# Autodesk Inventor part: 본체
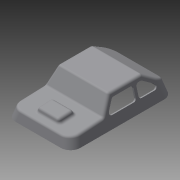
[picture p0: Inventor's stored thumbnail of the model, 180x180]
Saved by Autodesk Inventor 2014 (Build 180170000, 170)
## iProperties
Created: 2015-05
Part Number: 본체
Material: 일반
Document SubType Name: Modeling
Designer: net
Density: 1 g/cm^3
Appearance: 기본값
Author: net
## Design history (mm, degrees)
sketch "스케치1"
  geometry: L1 (0, 0)-(-76, 0); L2 (-76, 0)-(-67.694, 31); L3 (-67.694, 31)-(-8.306, 31); L4 (-8.306, 31)-(0, 0)
  constraints: 8 end point, 1 horizontal, 1 parallel
  dimensions: "d0" = 76 distance of L1.start L1.end; "d1" = 105 deg angle of L1 L2; "d2" = 105 deg angle of L1 L4; "d3" = 31 distance between parallel lines of L1 L3
extrude "돌출1" new body sketch "스케치1" distance "d4" = 122; taper "d5" = 0 deg
node "작업 평면1"
sketch "스케치2"
  geometry: L1 (0, 31)-(0, 0) reference; L2 (0, 31)-(122, 31) reference; L3 (122, 0)-(122, 31) reference; L4 (0, 0)-(122, 0) reference; L5 (0, 0)-(2.978, 11.113); L6 (2.978, 11.113)-(42, 13.158); L7 (42, 13.158)-(53.149, 31); L8 (92, 31)-(118.412, 13.392); L9 (118.412, 13.392)-(122, 0); 1 further point
  constraints: 10 end point, 2 point on line
  dimensions: "d7" = 105 deg angle of L4 L5; "d8" = 3 deg angle of L4 L6; "d9" = 125 deg angle of L6 L7; "d10" = 42 horizontal distance of L6.end point (0, 0); "d11" = 30 horizontal distance of L3.start L8.start; "d38" = 105 deg angle of L4 L9
extrude "돌출2" cut sketch "스케치2" stored distance "d13" = 122; taper "d14" = 0 deg
sketch "스케치3"
  geometry: L1 (-13.865, 118.412)-(-32.094, 92) reference; L2 (-32.094, 53.149)-(-32.094, 92) reference; L3 (-32.094, 53.149)-(-13.622, 42) reference; L4 (-13.865, 118.412)-(-32.094, 92) reference; L5 (-32.094, 53.149)-(-32.094, 92) reference; L6 (-32.094, 53.149)-(-13.622, 42) reference; L7 (-13.622, 42)-(-11.505, 2.978) reference; L8 (-11.505, 2.978)-(0, 0) reference; L9 (0, 0)-(0, 122) reference; L10 (0, 122)-(-13.865, 118.412) reference; L11 (-12.094, 46.917)-(-12.094, 80.917); L12 (-12.094, 80.917)-(-27.094, 80.917); L13 (-27.094, 80.917)-(-27.094, 55.971); L14 (-27.094, 55.971)-(-12.094, 46.917); L15 (-12.094, 84.175)-(-12.094, 112.175); L16 (-12.094, 112.175)-(-27.094, 90.442); L17 (-27.094, 84.175)-(-12.094, 84.175); L18 (-27.094, 84.175)-(-27.094, 90.442); 1 further point
  constraints: 16 end point, 5 parallel, 3 perpendicular, 1 vertical alignment
  dimensions: "d15" = 5 distance between parallel lines of L2 L13; "d16" = 5 distance between parallel lines of L14 L3; "d17" = 34 distance of L11.start L11.end; "d18" = 15 distance between parallel lines of L11 L13; "d19" = 5 distance between parallel lines of L1 L16; "d20" = 28 distance of L15.start L15.end; "d21" = 15 distance between parallel lines of L15 L18
  node "투영된 루프2"
feature "쉘1" dims "d22" = 2
extrude "돌출3" cut sketch "스케치3" distance "d23" = 5; taper "d24" = 0 deg
fillet "모깎기1" dims "d25" = 3
sketch "스케치4"
  geometry: L1 (0, 0)-(70.045, 0) reference; L2 (22.022, 27.445)-(48.022, 27.445); L3 (48.022, 27.445)-(48.022, 7.445); L4 (48.022, 7.445)-(22.022, 7.445); L5 (22.022, 7.445)-(22.022, 27.445); L6 (-2.978, -3.555)-(73.022, -3.555) reference; 2 further points
  constraints: 8 end point, 2 midpoint, 2 parallel, 1 horizontal, 1 perpendicular, 1 vertical alignment
  dimensions: "d26" = 26 distance of L2.start L2.end; "d27" = 20 distance of L4.end L2.start; "d28" = 11 distance between parallel lines of L6 L4
extrude "돌출4" join sketch "스케치4" distance "d29" = 5; taper "d30" = 0 deg
sketch "스케치5"
  geometry: L1 (0, 20)-(-5, 20) reference; L2 (-5, 0)-(-5, 20) reference; L3 (0, 0)-(-5, 0) reference; L4 (10.942, -11)-(17.327, 110.833) reference; L5 (0, -7.445)-(0, 31.631) reference; L6 (0, 0)-(-5, 1.82); L7 (0, 20)-(-5, 18.18)
  constraints: 4 end point, 2 point on line
extrude "돌출5" cut sketch "스케치5" stored distance "d34" = 5; taper "d35" = 0 deg
fillet "모깎기2" dims "d36" = 3
fillet "모깎기3" dims "d37" = 3
fillet "모깎기4" dims "d39" = 3
fillet "모깎기5" dims "d40" = 12
fillet "모깎기6" dims "d41" = 12
fillet "모깎기7" dims "d42" = 3
node "솔리드1"
mirror "대칭1"
node "투영된 루프1"
other parameters: "d6" = 38
